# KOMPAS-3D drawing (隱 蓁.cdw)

Referenced files in C:\Documents and Settings\501\Рабочий стол\: шкаф2.jpg, шкаф1.jpg
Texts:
  каб. воспитателя
  шкаф
  фасады 1 и 2
  шкаф 1
  фасады 3 и 4
  фасады с 5 по 16
  фасады с 17 по 20
  шкаф 2
  закрепить к стене
  каб. воспитателя-
Dimensions and other numbers on the sheet: 1200; 2100; 900; 300; 308; 78; 326; 642; 958; 500; 200; 1; 2; 3; 4; 394; 444; 441; 346; 400; 431; 484; 454; 100; 320; 440; 446; 640; 537; 539; 345; 474; 473; 501; 383; 411; 430; 198; 298; 398; 479; 558; 658; 758; 858; 30; 508; 376; 80; 538; 391; 493; 560; 38; 48; 710; 244; 184; 528; 2720; 304; 481; 387; 393; 342; 316; 468; 171; 242; 294; 491; 389; 492; 324; 460; 456; 40; 70; 826; 1306; 1648; 592; 1392; 536; 1328; 5; 6; 7; 8; 9; 10; 12; 11; 13; 14; 15; 16; 17; 18; 19; 20; 1:1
